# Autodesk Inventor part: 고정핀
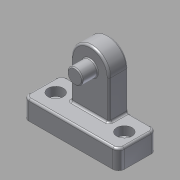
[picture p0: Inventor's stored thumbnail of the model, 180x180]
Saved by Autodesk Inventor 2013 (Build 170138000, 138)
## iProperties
Created: 2017-07
Part Number: 고정핀
Material: 알루미늄 6061
Document SubType Name: Modeling
Designer: mduedu
Density: 1 g/cm^3
Author: mduedu
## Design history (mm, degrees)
sketch "스케치1"
  geometry: L1 (-25, 0)-(25, 0); L2 (-25, 10)-(25, 10); L3 (-25, 0)-(-25, 10); L4 (25, 0)-(25, 10); L5 (-10, 10)-(10, 10); L6 (10, 10)-(10, 40); L7 (10, 40)-(-10, 40); L8 (-10, 40)-(-10, 10); 3 further points
  constraints: 16 end point, 4 parallel, 2 horizontal, 2 midpoint, 2 perpendicular, 1 coincident, 1 point on line, 1 vertical alignment
  dimensions: "d0" = 50 distance of L1.start L1.end; "d2" = 10 distance of L1.end L2.end; "d3" = 20 distance of L6.end L7.end; "d4" = 40 distance between parallel lines of L7 L1
extrude "돌출1" new body sketch "스케치1" stored distance "d5" = 20; taper "d6" = 0 deg
extrude "돌출2" join sketch "스케치1" distance "d7" = 10; taper "d8" = 0 deg
fillet "모깎기1"
sketch "스케치2"
  geometry: C1 r 4 at (0, 30); A1 r 10 centre (0, 30) between (10, 30) and (-10, 30) reference; 1 further point
  constraints: 1 centre point, 1 coincident
  dimensions: "d9" = 8 diameter of C1
extrude "돌출3" join sketch "스케치2" distance "d10" = 8; taper "d11" = 0 deg
fillet "모깎기2" dims "d12" = 0.5
fillet "모깎기3" dims "d13" = 1
fillet "모깎기4" dims "d14" = 1
fillet "모깎기5" dims "d15" = 3
fillet "모깎기6" dims "d16" = 1
chamfer "모따기1" distance "d18" = 0.5; stored, may be unused: second distance "d19" = 2, angle "d20" = 45 deg
sketch "스케치3"
  geometry: L1 (-16, 8)-(-16, -6) reference; L2 (34, -6)-(34, 8) reference; L3 (-16, 1)-(34, 1); L4 (-13, -9)-(31, -9) reference; L5 (9, 1)-(9, -9); 2 further points
  constraints: 4 end point, 3 midpoint, 1 point on line, 1 symmetric about line
  dimensions: "d21" = 7 distance from line of point (-9, 1) L1
sketch "스케치4"
  geometry: L1 (-16, 1)-(34, 1) reference; L2 (9, 1)-(9, -9) reference; 7 further points
  constraints: 2 coincident
hole "구멍1" sketch "스케치4" at (27, 1), (-9, 1) diameter "d22" = 4.5; stored, may be unused: countersink angle "d26" = 90 deg, drill point angle "d28" = 0 deg; dims "d23" = 6, "d24" = 8, "d25" = 4.6, "d27" = 8
node "솔리드1"
